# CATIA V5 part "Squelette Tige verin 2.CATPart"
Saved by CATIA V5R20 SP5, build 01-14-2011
Part number: Squelette Tige verin 2
Bounding box of the stored display mesh (mm): x -270 to -255.709, y -35.728 to 0, z -30 to 30
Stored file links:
  U:\CFAO\Thinkmotion\Squelette Tige verin 2.CATPart
  U:\CFAO\Thinkmotion\Bras Articule.CATProduct
  U:\CFAO\Thinkmotion\Squelette Corps verin 2.CATPart
  U:\CFAO\Thinkmotion\Squelette general.CATPart
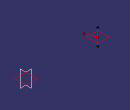
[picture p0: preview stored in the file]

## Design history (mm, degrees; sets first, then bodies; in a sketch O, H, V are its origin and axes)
Set1
  Line1: type PtPt, FirstPoint Point1, SecondPoint Point2
  Line2: type Normal, RefPoint Point1, RefSkin Plane2, Start -30, End 30
  Plane1: type OffsetPt, RefPlane xy-plane, RefPoint Point1
Set2
  Point1: linked copy from another document
  Point2: linked copy from another document
  Plane2: linked copy from another document
Body1 (main body)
